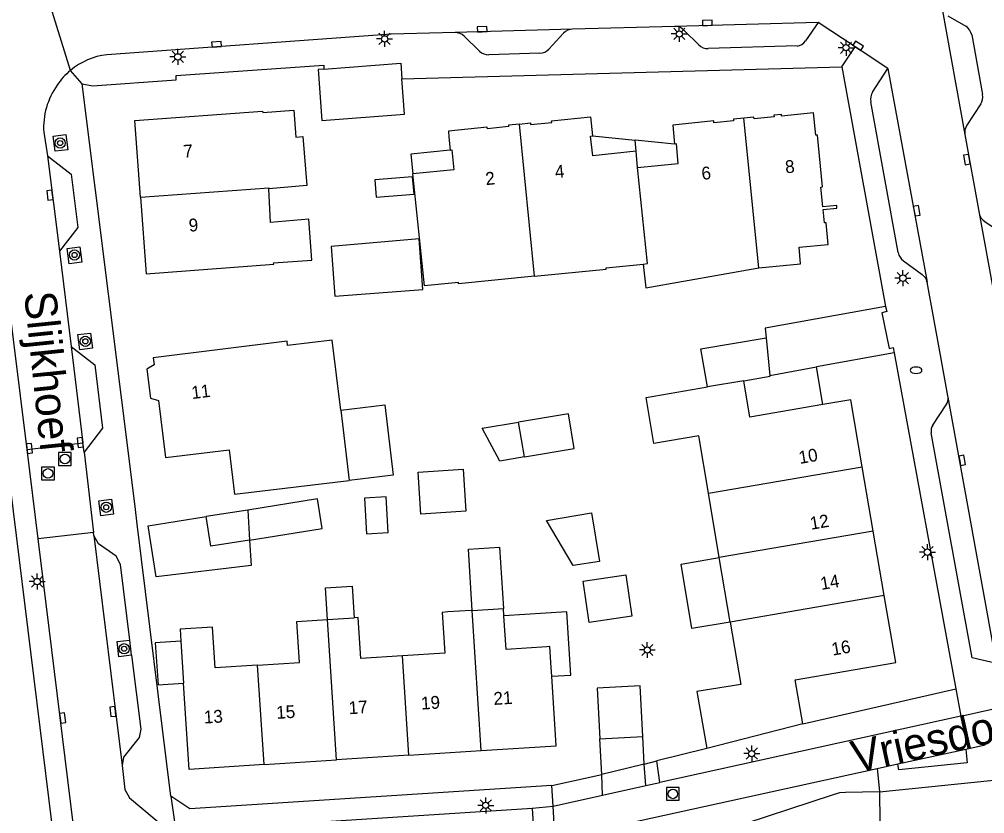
# Model space of a CAD drawing. Extents: x 140000 to 143000, y 403500 to 406000.
# Drawn here: x 140652.7 to 140728.3, y 403992.2 to 404054.4 of the extents above; entities that cross this region are included whole.
import ezdxf

# ---------------------------------------------------------------- set-up
doc = ezdxf.new("R2010")
doc.units = 0
for name, color, linetype in [('gg-afsc-erfafscheiding', 7, 'Continuous'), ('gg-anno-huisnummerreeks BGT', 7, 'Continuous'), ('gg-anno-openbare ruimte label', 7, 'Continuous'), ('gg-bbg-bijgebouw', 7, 'Continuous'), ('gg-bbg-hoofdgebouw', 7, 'Continuous'), ('gg-bbg-luifel en loopbrug', 7, 'Continuous'), ('gg-bbg-overig bouwwerk', 7, 'Continuous'), ('gg-bbg-tussenscheiding', 7, 'Continuous'), ('gg-knt-verharding', 7, 'Continuous'), ('gg-knt-verharding nz', 7, 'Continuous'), ('gt-grn-weggrens', 7, 'Continuous'), ('gt-symb-boom', 7, 'Continuous'), ('gt-symb-brandkraan', 7, 'Continuous'), ('gt-symb-kolk', 7, 'Continuous'), ('gt-symb-lichtmast', 7, 'Continuous'), ('gt-symb-rioolschacht', 7, 'Continuous')]:
    doc.layers.add(name, color=color, linetype=linetype)

# ---------------------------------------------------------------- blocks, each defined once
blk = doc.blocks.new('gt0-KOLK')
at = {"layer": 'gt-symb-kolk'}
blk.add_lwpolyline([(0, 0), (0.375, 0), (0.375, 0.4), (-0.375, 0.4), (-0.375, 0), (0, 0)], dxfattribs=at)
blk = doc.blocks.new('gt0-BOOM')
at = {"layer": 'gt-symb-boom'}
for radius in [0.4, 0.2]:
    blk.add_circle((0, 0), radius, dxfattribs=at)
blk = doc.blocks.new('gt0-LMAST')
at = {"layer": 'gt-symb-lichtmast'}
for p, q in [((-0.182, 0.173), (-0.447, 0.438)), ((-0.005, 0.246), (-0.005, 0.621)), ((0.172, 0.173), (0.437, 0.438)), ((-0.255, -0.004), (-0.63, -0.004)), ((-0.182, -0.181), (-0.447, -0.446)), ((-0.005, -0.254), (-0.005, -0.629)), ((0.437, -0.446), (0.172, -0.181)), ((0.245, -0.004), (0.62, -0.004))]:
    blk.add_line(p, q, dxfattribs=at)
blk.add_circle((-0.005, -0.004), 0.25, dxfattribs=at)
blk = doc.blocks.new('gt0-RS')
at = {"layer": 'gt-symb-rioolschacht'}
blk.add_lwpolyline([(-0.5, -0.5), (0.5, -0.5), (0.5, 0.5), (-0.5, 0.5)], close=True, dxfattribs=at)
blk.add_circle((0, 0), 0.375, dxfattribs=at)
blk = doc.blocks.new('gt0-BR')
at = {"layer": 'gt-symb-brandkraan'}
for centre, radius, start, end in [((-0.244, 0), 0.206, 107.56694, 252.43307), ((0.599, -2.664), 3, 106.89205, 107.56694), ((0, -0.691), 0.938, 73.10799, 106.89205), ((-0.599, -2.664), 3, 72.43309, 73.10799), ((0.244, 0), 0.206, 287.56695, 72.43309), ((0.599, 2.664), 3, 252.43307, 253.10797), ((0, 0.691), 0.938, 253.10797, 286.89206), ((-0.599, 2.664), 3, 286.89206, 287.56695)]:
    blk.add_arc(centre, radius, start, end, dxfattribs=at)

msp = doc.modelspace()

# ---------------------------------------------------------------- linework, layer by layer
at = {"layer": 'gg-afsc-erfafscheiding'}
msp.add_lwpolyline([(140720.042, 403993.941), (140720.089, 403989.294), (140722.989, 403989.327)], dxfattribs=at)
at = {"layer": 'gg-bbg-bijgebouw'}
for p, q in [((140711.165, 404029.473), (140711.46, 404026.526)), ((140721.188, 404028.287), (140715.102, 404027.185)), ((140711.46, 404026.526), (140715.102, 404027.185)), ((140692.239, 404020.138), (140691.784, 404022.871)), ((140670.581, 404015.988), (140667.328, 404015.472)), ((140698.141, 403998.076), (140701.508, 403998.259)), ((140701.625, 403996.111), (140701.508, 403998.259)), ((140698.293, 403995.29), (140698.141, 403998.076)), ((140701.625, 403996.111), (140698.293, 403995.29))]:
    msp.add_line(p, q, dxfattribs=at)
for points in [[(140676.543, 404050.496), (140676.101, 404050.463), (140676.397, 404046.477), (140682.864, 404046.96), (140682.657, 404049.731)], [(140676.543, 404050.496), (140682.566, 404050.947), (140682.657, 404049.731)], [(140677.127, 404036.619), (140677.412, 404032.731), (140684.291, 404033.231), (140684.002, 404037.21), (140677.127, 404036.619)], [(140720.517, 404031.921), (140711.09, 404030.226), (140711.165, 404029.473)], [(140720.517, 404031.921), (140720.598, 404031.509), (140720.208, 404031.423), (140720.798, 404028.635), (140721.101, 404028.699), (140721.188, 404028.287)], [(140692.239, 404020.138), (140690.314, 404019.817), (140688.923, 404022.394), (140691.784, 404022.871)], [(140684.139, 404015.672), (140683.928, 404018.951), (140687.447, 404019.177), (140687.657, 404015.898), (140684.139, 404015.672)], [(140670.732, 404013.639), (140676.421, 404014.542), (140676.054, 404016.857), (140670.581, 404015.988)], [(140696.071, 404011.634), (140693.967, 404015.179), (140697.503, 404015.772), (140698.111, 404011.96), (140696.071, 404011.634)], [(140670.732, 404013.639), (140667.695, 404013.157), (140667.328, 404015.472)], [(140700.181, 404010.916), (140700.652, 404007.67), (140697.31, 404007.185), (140696.839, 404010.431), (140700.181, 404010.916)]]:
    msp.add_lwpolyline(points, dxfattribs=at)
at = {"layer": 'gg-bbg-hoofdgebouw'}
for p, q in [((140701.102, 404042.798), (140700.995, 404044.062)), ((140709.408, 404026.106), (140706.566, 404025.619)), ((140677.861, 404023.795), (140678.522, 404018.304)), ((140719.547, 404014.331), (140718.683, 404019.375)), ((140707.495, 404012.264), (140706.64, 404017.31)), ((140720.412, 404009.289), (140719.547, 404014.331)), ((140708.349, 404007.22), (140707.495, 404012.264)), ((140688.161, 404008.13), (140690.599, 404008.286)), ((140690.636, 404007.707), (140690.599, 404008.286)), ((140676.824, 404007.413), (140678.921, 404007.546)), ((140665.346, 404005.724), (140665.56, 404002.431)), ((140714.024, 403999.244), (140706.509, 403997.315)), ((140683.198, 403996.796), (140677.53, 403996.432)), ((140683.198, 403996.796), (140688.866, 403997.16)), ((140671.862, 403996.068), (140677.53, 403996.432))]:
    msp.add_line(p, q, dxfattribs=at)
for points in [[(140662.184, 404040.463), (140661.745, 404046.457), (140671.746, 404047.192), (140671.755, 404047.086), (140674.191, 404047.266), (140674.339, 404045.173), (140674.89, 404045.215), (140675.205, 404041.369), (140672.247, 404041.122)], [(140691.851, 404046.188), (140692.716, 404046.274), (140692.726, 404046.153), (140694.377, 404046.321), (140694.365, 404046.44), (140697.417, 404046.749), (140697.571, 404045.27)], [(140709.408, 404046.658), (140708.607, 404046.577), (140708.621, 404046.438), (140707.079, 404046.282), (140707.059, 404046.433), (140703.856, 404046.113), (140703.995, 404044.625)], [(140710.58, 404034.95), (140713.859, 404035.259), (140713.738, 404036.562), (140716.028, 404036.775), (140715.871, 404038.468), (140715.731, 404038.455), (140715.633, 404039.5), (140716.709, 404039.601), (140716.689, 404039.81), (140715.597, 404039.708), (140715.444, 404041.26), (140715.583, 404041.274), (140715.182, 404045.327), (140715.042, 404045.307), (140714.879, 404047.062), (140712.369, 404046.817), (140712.355, 404046.948), (140711.765, 404046.886), (140711.78, 404046.747), (140710.225, 404046.584), (140710.209, 404046.739), (140709.408, 404046.658)], [(140691.851, 404046.188), (140690.986, 404046.103), (140690.998, 404045.984), (140689.346, 404045.82), (140689.334, 404045.938), (140686.29, 404045.635), (140686.337, 404045.16), (140686.438, 404044.152)], [(140700.995, 404044.062), (140697.587, 404043.7), (140697.422, 404045.251), (140697.571, 404045.27)], [(140701.102, 404042.798), (140704.279, 404043.095), (140704.134, 404044.638), (140703.995, 404044.625)], [(140686.438, 404044.152), (140686.567, 404044.165), (140686.722, 404042.603), (140683.518, 404042.284)], [(140693.044, 404034.275), (140687.088, 404033.685), (140687.078, 404033.785), (140684.42, 404033.517), (140683.518, 404042.284)], [(140662.184, 404040.463), (140662.623, 404034.479), (140672.615, 404035.217), (140672.608, 404035.327), (140675.6, 404035.539), (140675.37, 404038.737), (140672.371, 404038.475), (140672.247, 404041.122)], [(140693.044, 404034.275), (140698.65, 404034.83), (140698.64, 404034.935), (140701.548, 404035.231)], [(140701.548, 404035.231), (140701.743, 404033.362), (140710.58, 404034.95)], [(140677.861, 404023.795), (140677.199, 404029.29), (140673.706, 404028.87), (140673.668, 404029.19), (140663.192, 404027.907), (140663.26, 404027.345), (140662.697, 404027.003), (140662.98, 404024.732), (140663.602, 404024.544), (140664.144, 404020.091), (140669.13, 404020.697), (140669.551, 404017.222), (140678.522, 404018.304)], [(140715.606, 404024.241), (140709.899, 404023.262), (140709.408, 404026.106)], [(140706.64, 404017.31), (140705.883, 404021.78), (140702.382, 404021.197), (140701.773, 404024.798), (140706.566, 404025.619)], [(140718.683, 404019.375), (140717.784, 404024.614), (140715.606, 404024.241)], [(140714.024, 403999.244), (140713.426, 404002.697), (140721.311, 404004.049), (140720.412, 404009.289)], [(140688.161, 404008.13), (140688.064, 404008.124), (140686.254, 404008.009), (140685.804, 404007.98), (140686.006, 404004.778), (140682.698, 404004.569)], [(140671.362, 404003.85), (140674.628, 404004.058), (140674.426, 404007.26), (140676.824, 404007.413)], [(140682.698, 404004.569), (140679.425, 404004.362), (140679.22, 404007.565), (140678.921, 404007.546)], [(140694.389, 404002.984), (140694.346, 404003.662), (140694.243, 404005.304), (140694.006, 404005.289), (140690.806, 404005.083), (140690.636, 404007.707)], [(140708.349, 404007.22), (140709.178, 404002.328), (140705.726, 404001.78), (140706.509, 403997.315)], [(140671.362, 404003.85), (140668.038, 404003.639), (140667.831, 404006.829), (140665.285, 404006.655), (140665.346, 404005.724)], [(140688.866, 403997.16), (140694.731, 403997.537), (140694.389, 404002.984)], [(140671.862, 403996.068), (140665.999, 403995.691), (140665.56, 404002.431)]]:
    msp.add_lwpolyline(points, dxfattribs=at)
at = {"layer": 'gg-bbg-luifel en loopbrug'}
for p, q in [((140697.571, 404045.27), (140700.921, 404044.934)), ((140700.995, 404044.062), (140700.921, 404044.934)), ((140703.995, 404044.625), (140700.921, 404044.934)), ((140715.606, 404024.241), (140715.102, 404027.185))]:
    msp.add_line(p, q, dxfattribs=at)
for points in [[(140686.438, 404044.152), (140683.358, 404043.835), (140683.518, 404042.284)], [(140680.627, 404040.48), (140683.6, 404040.711), (140683.495, 404042.063), (140680.522, 404041.832), (140680.627, 404040.48)], [(140706.566, 404025.619), (140706.056, 404028.597), (140711.165, 404029.473)], [(140709.408, 404026.106), (140711.467, 404026.459), (140711.46, 404026.526)], [(140677.861, 404023.795), (140681.304, 404024.21), (140681.966, 404018.719), (140678.522, 404018.304)], [(140692.239, 404020.138), (140696.142, 404020.788), (140695.687, 404023.521), (140691.784, 404022.871)], [(140670.732, 404013.639), (140670.86, 404011.643), (140663.418, 404010.756), (140662.785, 404014.751), (140667.328, 404015.472)], [(140688.161, 404008.13), (140687.853, 404012.92), (140690.291, 404013.077), (140690.599, 404008.286)], [(140708.349, 404007.22), (140705.357, 404006.707), (140704.503, 404011.751), (140707.495, 404012.264)], [(140676.824, 404007.413), (140676.666, 404009.908), (140678.762, 404010.041), (140678.921, 404007.546)], [(140694.389, 404002.984), (140695.872, 404003.077), (140695.562, 404008.018), (140690.636, 404007.707)], [(140665.346, 404005.724), (140663.35, 404005.588), (140663.575, 404002.296), (140665.56, 404002.431)], [(140701.508, 403998.259), (140701.292, 404002.238), (140697.925, 404002.055), (140698.141, 403998.076)]]:
    msp.add_lwpolyline(points, dxfattribs=at)
at = {"layer": 'gg-bbg-overig bouwwerk'}
msp.add_lwpolyline([(140679.715, 404016.91), (140679.881, 404014.115), (140681.578, 404014.216), (140681.412, 404017.011), (140679.715, 404016.91)], dxfattribs=at)
at = {"layer": 'gg-bbg-tussenscheiding'}
for p, q in [((140710.58, 404034.95), (140709.408, 404046.658)), ((140693.044, 404034.275), (140691.851, 404046.188)), ((140706.64, 404017.31), (140718.683, 404019.375)), ((140670.581, 404015.988), (140670.732, 404013.639)), ((140719.547, 404014.331), (140707.495, 404012.264)), ((140720.412, 404009.289), (140708.349, 404007.22)), ((140688.866, 403997.16), (140688.161, 404008.13)), ((140677.53, 403996.432), (140676.824, 404007.413)), ((140683.198, 403996.796), (140682.698, 404004.569)), ((140671.862, 403996.068), (140671.362, 404003.85))]:
    msp.add_line(p, q, dxfattribs=at)
for points in [[(140701.548, 404035.231), (140701.869, 404035.264), (140701.102, 404042.798)], [(140662.184, 404040.463), (140672.243, 404041.202), (140672.247, 404041.122)]]:
    msp.add_lwpolyline(points, dxfattribs=at)
at = {"layer": 'gg-knt-verharding'}
for p, q in [((140724.917, 404055.337), (140726.723, 404045.37)), ((140715.242, 404054.145), (140704.015, 404053.833)), ((140715.242, 404054.145), (140714.238, 404052.693)), ((140718.124, 404052.233), (140715.242, 404054.145)), ((140725.392, 404054.658), (140726.781, 404053.838)), ((140696.013, 404053.62), (140686.809, 404053.351)), ((140695.31, 404053.295), (140694.154, 404052.055)), ((140704.015, 404053.833), (140696.013, 404053.62)), ((140705.89, 404052.385), (140704.724, 404053.542)), ((140688.734, 404051.892), (140687.519, 404053.067)), ((140727.257, 404053.157), (140728.109, 404048.491)), ((140713.592, 404052.296), (140706.62, 404052.099)), ((140720.699, 404050.525), (140718.124, 404052.233)), ((140693.449, 404051.73), (140689.456, 404051.617)), ((140682.657, 404049.731), (140717.09, 404050.674)), ((140717.09, 404050.674), (140720.517, 404031.921)), ((140719.496, 404048.691), (140720.699, 404050.525)), ((140721.507, 404036.134), (140719.35, 404047.931)), ((140727.962, 404047.764), (140726.87, 404046.096)), ((140654.62, 404045.549), (140654.921, 404043.691)), ((140726.723, 404045.37), (140727.84, 404039.207)), ((140654.921, 404043.691), (140655.845, 404036.248)), ((140727.84, 404039.207), (140731.99, 404016.328)), ((140728.27, 404038.553), (140729.798, 404037.536)), ((140655.845, 404036.248), (140656.772, 404028.78)), ((140721.916, 404035.478), (140723.366, 404034.418)), ((140653.312, 404020.713), (140651.732, 404033.531)), ((140656.772, 404028.78), (140657.681, 404021.24)), ((140721.188, 404028.287), (140726.001, 404002.008)), ((140729.203, 404003.988), (140725.41, 404024.828)), ((140724.2, 404022.639), (140725.265, 404024.209)), ((140653.312, 404020.713), (140657.681, 404021.24)), ((140657.769, 404020.51), (140657.681, 404021.24)), ((140654.173, 404013.729), (140653.312, 404020.713)), ((140657.769, 404020.51), (140658.503, 404014.236)), ((140658.503, 404014.236), (140654.173, 404013.729)), ((140658.53, 404014.004), (140658.503, 404014.236)), ((140658.53, 404014.004), (140660.746, 403995.983)), ((140661.498, 404004.624), (140661.352, 404005.81)), ((140714.024, 403999.244), (140726.001, 404002.008)), ((140726.001, 404002.008), (140726.394, 403999.862)), ((140726.394, 403999.862), (140736.953, 404002.251)), ((140726.394, 403999.862), (140702.838, 403994.669)), ((140728.298, 403997.598), (140726.793, 403997.255)), ((140706.509, 403997.315), (140702.618, 403996.356)), ((140720.042, 403993.941), (140751.034, 403997.096)), ((140726.793, 403997.255), (140721.472, 403996.107)), ((140701.625, 403996.111), (140702.618, 403996.356)), ((140701.746, 403994.428), (140701.625, 403996.111)), ((140702.838, 403994.669), (140702.618, 403996.356)), ((140721.472, 403996.107), (140719.854, 403995.738)), ((140694.38, 403994.43), (140698.293, 403995.29)), ((140719.854, 403995.738), (140694.645, 403990.221)), ((140698.357, 403993.68), (140698.293, 403995.29)), ((140694.481, 403992.826), (140694.38, 403994.43)), ((140698.357, 403993.68), (140701.746, 403994.428)), ((140701.746, 403994.428), (140702.838, 403994.669)), ((140694.481, 403992.826), (140698.357, 403993.68)), ((140694.645, 403990.221), (140694.481, 403992.826)), ((140664.947, 403990.851), (140692.847, 403992.657)), ((140692.847, 403992.657), (140694.794, 403962.129))]:
    msp.add_line(p, q, dxfattribs=at)
for points in [[(140615.699, 404080.633), (140615.983, 404080.638), (140635.008, 404078.847), (140638.477, 404076.282), (140642.369, 404054.461), (140650.122, 404032.814), (140655.697, 403987.762), (140658.721, 403939.199)], [(140686.809, 404053.351), (140682.807, 404053.241), (140681.818, 404053.23), (140659.558, 404051.607)], [(140657.62, 404049.324), (140658.445, 404049.169), (140664.989, 404049.648), (140664.987, 404049.982), (140676.53, 404050.809), (140676.543, 404050.496)], [(140664.553, 403993.598), (140661.941, 404014.878), (140661.771, 404016.267), (140657.62, 404049.324)], [(140655.508, 404044.06), (140655.362, 404045.246), (140656.355, 404045.369), (140656.501, 404044.182), (140655.508, 404044.06)], [(140654.921, 404043.691), (140656.761, 404042.257), (140657.279, 404038.089), (140655.845, 404036.248)], [(140656.6, 404035.263), (140656.453, 404036.449), (140657.446, 404036.571), (140657.592, 404035.385), (140656.6, 404035.263)], [(140725.41, 404024.828), (140725.395, 404024.91), (140724.761, 404028.378), (140723.773, 404033.807)], [(140657.443, 404028.527), (140657.297, 404029.713), (140658.29, 404029.836), (140658.436, 404028.649), (140657.443, 404028.527)], [(140656.772, 404028.78), (140658.613, 404027.346), (140659.229, 404022.384), (140657.769, 404020.51)], [(140729.203, 404003.988), (140727.286, 404004.418), (140724.081, 404022.029)], [(140659.079, 404015.528), (140658.933, 404016.714), (140659.926, 404016.836), (140660.072, 404015.65), (140659.079, 404015.528)], [(140661.352, 404005.81), (140660.622, 404011.731), (140660.289, 404012.376), (140658.9, 404013.336), (140658.53, 404014.004)], [(140659.058, 403960.869), (140657.359, 403987.877), (140654.173, 404013.729)], [(140661.498, 404004.624), (140660.506, 404004.501), (140660.359, 404005.687), (140661.352, 404005.81)], [(140661.498, 404004.624), (140662.21, 403998.844), (140662.079, 403998.19), (140660.848, 403996.656), (140660.746, 403995.983)], [(140726.793, 403997.255), (140726.89, 403996.206), (140721.545, 403995.654), (140721.472, 403996.107)], [(140660.746, 403995.983), (140660.968, 403994.124), (140661.338, 403993.459), (140664.224, 403991.043), (140664.947, 403990.851)], [(140719.854, 403995.738), (140719.876, 403995.531), (140720.042, 403993.941)], [(140694.38, 403994.43), (140666.046, 403992.612), (140664.553, 403993.598)], [(140720.042, 403993.941), (140717.377, 403993.874), (140716.911, 403993.862), (140716.325, 403993.67), (140707.904, 403990.905), (140694.685, 403989.591)]]:
    msp.add_lwpolyline(points, dxfattribs=at)
for centre, radius, start, end in [((140686.813, 404052.332), 1.019, 46.15723, 90.23995), ((140696.043, 404052.631), 0.989, 91.76242, 137.8602), ((140704.024, 404052.845), 0.988, 44.86186, 90.508), ((140726.274, 404052.977), 1, 10.39839, 59.50656), ((140713.501, 404053.168), 0.877, 275.95915, 327.18655), ((140689.415, 404052.593), 0.977, 225.86591, 272.43178), ((140693.435, 404052.688), 0.959, 270.86349, 318.63524), ((140706.579, 404053.069), 0.971, 224.79799, 272.41343), ((140660.162, 404046.25), 5.391, 96.42822, 129.81347), ((140660.165, 404046.25), 5.393, 129.83673, 146.49416), ((140660.301, 404045.919), 5.693, 144.4684, 183.72313), ((140720.322, 404048.138), 0.994, 146.20482, 192.0465), ((140727.124, 404048.312), 1.002, 326.83483, 10.30291), ((140727.71, 404045.548), 1.003, 146.88045, 190.22663), ((140728.829, 404039.389), 1.005, 190.40904, 236.24019), ((140722.475, 404036.282), 0.979, 188.69785, 235.18721), ((140722.814, 404033.609), 0.979, 11.64858, 55.68826), ((140724.519, 404024.71), 0.899, 326.10401, 7.52847), ((140725.018, 404022.163), 0.947, 149.79621, 188.12632)]:
    msp.add_arc(centre, radius, start, end, dxfattribs=at)
at = {"layer": 'gg-knt-verharding nz'}
msp.add_line((140720.699, 404050.525), (140723.773, 404033.807), dxfattribs=at)
at = {"layer": 'gt-grn-weggrens'}
for p, q in [((140656.71, 404050.391), (140654.85, 404056.348)), ((140717.09, 404050.674), (140718.124, 404052.233)), ((140657.62, 404049.324), (140656.71, 404050.391)), ((140664.553, 403993.598), (140664.947, 403990.851)), ((140692.847, 403992.657), (140694.481, 403992.826))]:
    msp.add_line(p, q, dxfattribs=at)

# ---------------------------------------------------------------- block references
at = {"layer": 'gt-symb-boom'}
for p in [(140655.901, 404044.703), (140657.033, 404035.943), (140657.874, 404029.186), (140659.515, 404016.204), (140660.91, 404005.13)]:
    msp.add_blockref('gt0-BOOM', p, dxfattribs=at)
at = {"layer": 'gt-symb-brandkraan'}
msp.add_blockref('gt0-BR', (140722.899, 404026.929), dxfattribs=at)
at = {"layer": 'gt-symb-kolk'}
for p, rotation in [((140706.568, 404053.904), 1.590019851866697), ((140688.941, 404053.413), 1.6706868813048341), ((140668.163, 404052.234), 4.167837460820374), ((140718.259, 404052.144), -33.558024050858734), ((140727.076, 404043.446), 100.54232037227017), ((140655.298, 404040.651), 97.07897394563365), ((140722.751, 404039.366), -79.58111212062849), ((140657.675, 404021.292), 96.87578398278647), ((140653.304, 404020.782), -82.97006783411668), ((140726.318, 404019.839), -79.6872135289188), ((140660.223, 404000.24), 97.01391414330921), ((140655.903, 403999.692), -82.9780767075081)]:
    msp.add_blockref('gt0-KOLK', p, dxfattribs=dict(at, rotation=rotation))
at = {"layer": 'gt-symb-lichtmast'}
for p in [(140681.305, 404052.854), (140704.372, 404053.242), (140717.419, 404052.166), (140665.119, 404051.449), (140721.874, 404034.135), (140723.789, 404012.694), (140654.109, 404010.39), (140701.868, 404005.038), (140710.039, 403996.929), (140689.218, 403992.882)]:
    msp.add_blockref('gt0-LMAST', p, dxfattribs=at)
at = {"layer": 'gt-symb-rioolschacht'}
for p in [(140656.276, 404019.983), (140654.95, 404018.85), (140703.862, 403993.775)]:
    msp.add_blockref('gt0-RS', p, dxfattribs=at)

# ---------------------------------------------------------------- texts
at = {"layer": 'gg-anno-huisnummerreeks BGT'}
for s, rotation, p in [('7', 4.1, (140665.579, 404043.552)), ('4', 5.8, (140694.676, 404041.949)), ('6', 5.7, (140706.149, 404041.819)), ('8', 5.5, (140712.695, 404042.328)), ('2', 5.7, (140689.237, 404041.405)), ('9', 4.2, (140666.004, 404037.763)), ('11', 7.1, (140666.236, 404024.666)), ('10', 9.7, (140713.799, 404019.589)), ('12', 9.7, (140714.682, 404014.436)), ('14', 9.7, (140715.489, 404009.727)), ('16', 9.7, (140716.371, 404004.591)), ('19', 3.6, (140684.182, 404000.367)), ('21', 3.6, (140689.85, 404000.731)), ('15', 3.6, (140672.846, 403999.639)), ('17', 3.6, (140678.514, 404000.003)), ('13', 3.6, (140667.178, 403999.275))]:
    msp.add_text(s, height=1, rotation=rotation, dxfattribs=at).set_placement(p)
at = {"layer": 'gg-anno-openbare ruimte label'}
for s, rotation, p in [('Slijkhoef', 275.9, (140653.077, 404032.986)), ('Vriesdonk', 12.4, (140718.15, 403995.408))]:
    msp.add_text(s, height=2.5, rotation=rotation, dxfattribs=at).set_placement(p)

doc.saveas('drawing.dxf')
